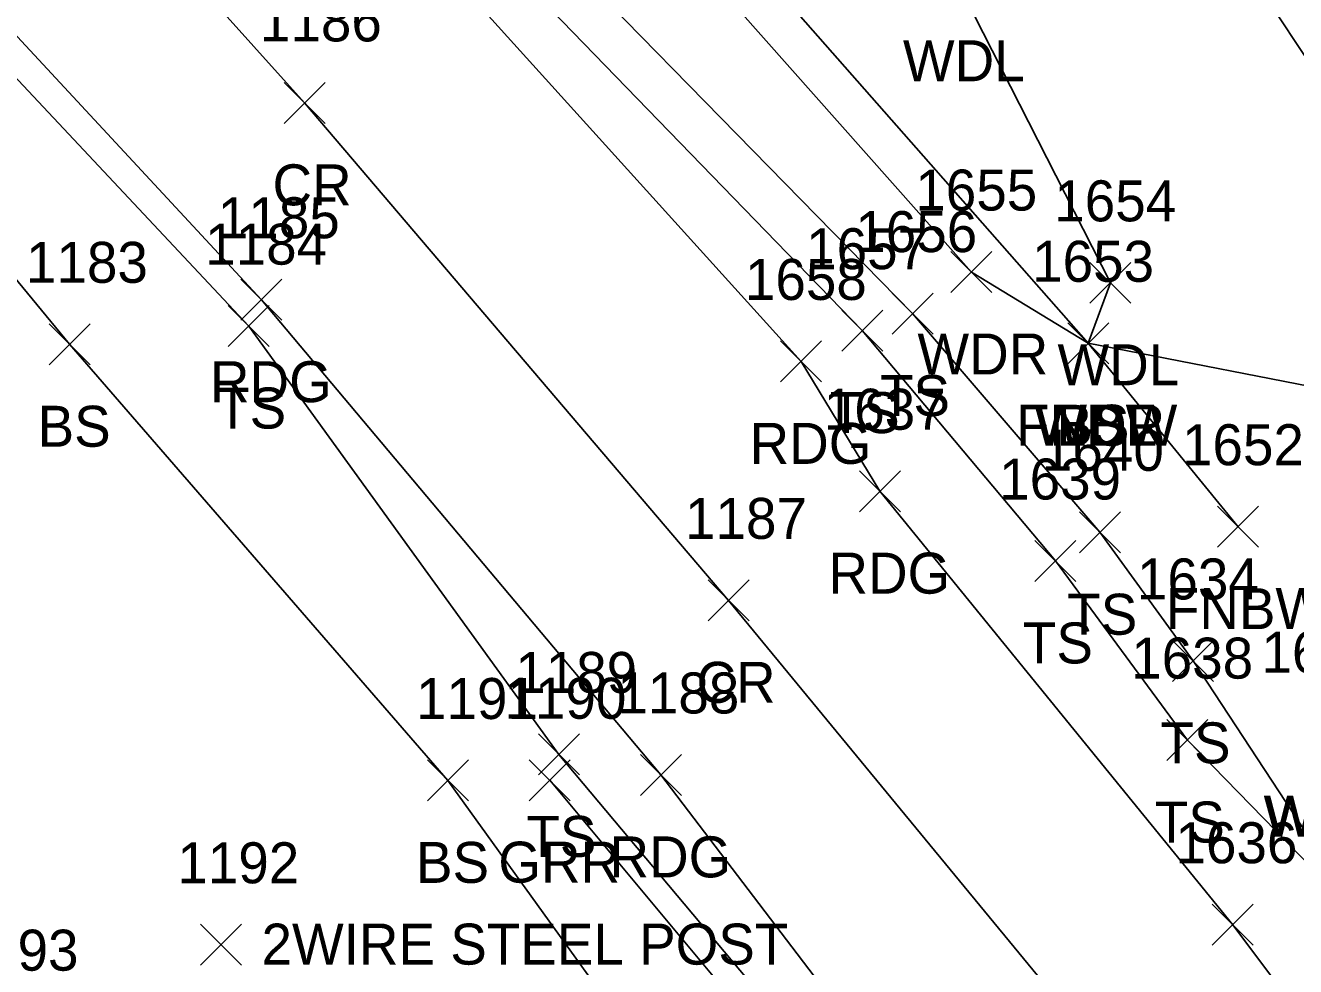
# Model space of a CAD drawing. Extents: x 1469310 to 1475157, y 493997 to 498873.
# Drawn here: x 1469498.4 to 1469560.4, y 498605.4 to 498651.4 of the extents above; entities that cross this region are included whole.
import ezdxf

# ---------------------------------------------------------------- set-up
doc = ezdxf.new("R2010")
doc.units = 0
for name, color, linetype in [('L_A', 7, 'Continuous'), ('L_I', 7, 'Continuous'), ('L_TIC', 7, 'Continuous'), ('LAWA', 7, 'Continuous'), ('LELB', 7, 'Continuous'), ('LFNC', 7, 'Continuous'), ('P_A', 7, 'Continuous'), ('P_I', 7, 'Continuous'), ('P_TIC', 7, 'Continuous'), ('PEU', 7, 'Continuous'), ('PRC', 7, 'Continuous'), ('R_A', 7, 'Continuous'), ('R_C', 7, 'Continuous'), ('R_I', 7, 'Continuous'), ('R_TIC', 7, 'Continuous'), ('RGR', 7, 'Continuous')]:
    doc.layers.add(name, color=color, linetype=linetype)

msp = doc.modelspace()

# ---------------------------------------------------------------- linework, layer by layer
at = {"layer": 'L_TIC'}
for points in [[(1469543.555, 498638.347), (1469545.555, 498640.347)], [(1469545.555, 498638.347), (1469543.555, 498640.347)], [(1469550.335, 498637.82), (1469552.335, 498639.82)], [(1469552.335, 498637.82), (1469550.335, 498639.82)], [(1469540.68, 498636.319), (1469542.68, 498638.319)], [(1469542.68, 498636.319), (1469540.68, 498638.319)], [(1469508.281, 498635.708), (1469510.281, 498637.708)], [(1469510.281, 498635.708), (1469508.281, 498637.708)], [(1469538.227, 498635.486), (1469540.227, 498637.486)], [(1469540.227, 498635.486), (1469538.227, 498637.486)], [(1469499.535, 498634.821), (1469501.535, 498636.821)], [(1469501.535, 498634.821), (1469499.535, 498636.821)], [(1469549.256, 498634.871), (1469551.256, 498636.871)], [(1469551.256, 498634.871), (1469549.256, 498636.871)], [(1469549.256, 498634.871), (1469551.256, 498636.871)], [(1469551.256, 498634.871), (1469549.256, 498636.871)], [(1469549.256, 498634.871), (1469551.256, 498636.871)], [(1469551.256, 498634.871), (1469549.256, 498636.871)], [(1469549.256, 498634.871), (1469551.256, 498636.871)], [(1469551.256, 498634.871), (1469549.256, 498636.871)], [(1469556.57, 498625.919), (1469558.57, 498627.919)], [(1469558.57, 498625.919), (1469556.57, 498627.919)], [(1469549.821, 498625.646), (1469551.821, 498627.646)], [(1469551.821, 498625.646), (1469549.821, 498627.646)], [(1469547.655, 498624.245), (1469549.655, 498626.245)], [(1469549.655, 498624.245), (1469547.655, 498626.245)], [(1469554.371, 498619.368), (1469556.371, 498621.368)], [(1469556.371, 498619.368), (1469554.371, 498621.368)], [(1469554.093, 498615.504), (1469556.093, 498617.504)], [(1469556.093, 498615.504), (1469554.093, 498617.504)], [(1469523.422, 498614.805), (1469525.422, 498616.805)], [(1469525.422, 498614.805), (1469523.422, 498616.805)], [(1469518.003, 498613.534), (1469520.003, 498615.534)], [(1469520.003, 498613.534), (1469518.003, 498615.534)], [(1469506.922, 498605.516), (1469508.922, 498607.516)], [(1469508.922, 498605.516), (1469506.922, 498607.516)]]:
    msp.add_lwpolyline(points, dxfattribs=at)
at = {"layer": 'LAWA'}
for points in [[(1469550.256, 498635.871), (1469551.335, 498638.82), (1469543.791, 498653.658), (1469517.004, 498693.687), (1469493.697, 498717.291), (1469464.727, 498743.888), (1469442.449, 498767.361), (1469415.626, 498791.262), (1469396.511, 498809.173), (1469374.233, 498838.066)], [(1469550.256, 498635.871), (1469544.555, 498639.347), (1469529.257, 498656.591), (1469521.268, 498666.888), (1469499.096, 498691), (1469482.906, 498705.537), (1469469.317, 498718.602), (1469451.077, 498739.432), (1469431.272, 498758.582), (1469415.669, 498776.754), (1469392.183, 498799.734), (1469384.544, 498811.213)]]:
    msp.add_lwpolyline(points, dxfattribs=at)
at = {"layer": 'LELB'}
for points in [[(1469689.874, 498657.87), (1469664.198, 498669.39), (1469609.729, 498671.933), (1469582.144, 498658.759), (1469563.399, 498646.025), (1469554.478, 498659.448), (1469546.055, 498676.671), (1469525.383, 498698.234), (1469503.854, 498725.442), (1469472.452, 498754.543), (1469455.127, 498777.294), (1469419.867, 498802.33), (1469400.99, 498819.039), (1469383.055, 498844.763)], [(1469596.337, 498559.709), (1469578.349, 498585.399), (1469563.744, 498607.627), (1469555.371, 498620.368), (1469550.821, 498626.646), (1469541.68, 498637.319), (1469517.52, 498662.002), (1469494.243, 498687.266), (1469477.199, 498705.84), (1469448.358, 498735.299), (1469427.592, 498756.343), (1469413.618, 498771.296), (1469390.023, 498797.181), (1469364.143, 498823.885)], [(1469563.744, 498607.627), (1469555.093, 498616.504), (1469548.655, 498625.245), (1469539.227, 498636.486), (1469516.208, 498660.231), (1469491.998, 498685.049), (1469474.245, 498704.181), (1469446.062, 498733.487), (1469425.868, 498754.547), (1469411.994, 498769.104), (1469387.947, 498794.99), (1469362.089, 498822.046)], [(1469416.823, 498734.314), (1469446.326, 498703.097), (1469470.885, 498677.648), (1469509.281, 498636.708), (1469524.422, 498615.805), (1469544.375, 498592.02), (1469564.878, 498563.16), (1469574.599, 498542.858), (1469576.567, 498532.675), (1469562.977, 498525.948), (1469548.2, 498517.369), (1469540.614, 498511.222), (1469554.066, 498484.991), (1469566.508, 498459.59)], [(1469413.419, 498730.944), (1469442.517, 498698.703), (1469468.453, 498674.773), (1469500.535, 498635.821), (1469519.003, 498614.534), (1469533.172, 498594.862), (1469544.52, 498587.119), (1469562.893, 498554.703), (1469567.788, 498543.524), (1469559.261, 498528.602), (1469545.395, 498521.66), (1469536.791, 498513.026)], [(1469563.61, 498633.273), (1469550.256, 498635.871)]]:
    msp.add_lwpolyline(points, dxfattribs=at)
at = {"layer": 'LFNC'}
msp.add_lwpolyline([(1469557.57, 498626.919), (1469550.256, 498635.871), (1469522.293, 498667.624), (1469500.255, 498692.907), (1469472.784, 498720.334), (1469454.313, 498738.912), (1469435.585, 498759.186), (1469416.3, 498780.923), (1469395.195, 498801.33), (1469384.544, 498811.213), (1469367.117, 498829.454)], dxfattribs=at)
at = {"layer": 'P_TIC'}
for points in [[(1469511.008, 498646.602), (1469513.008, 498648.602)], [(1469513.008, 498646.602), (1469511.008, 498648.602)], [(1469508.9, 498636.995), (1469510.9, 498638.995)], [(1469510.9, 498636.995), (1469508.9, 498638.995)], [(1469535.237, 498633.985), (1469537.237, 498635.985)], [(1469537.237, 498633.985), (1469535.237, 498635.985)], [(1469539.085, 498627.651), (1469541.085, 498629.651)], [(1469541.085, 498627.651), (1469539.085, 498629.651)], [(1469531.7, 498622.323), (1469533.7, 498624.323)], [(1469533.7, 498622.323), (1469531.7, 498624.323)], [(1469528.399, 498613.803), (1469530.399, 498615.803)], [(1469530.399, 498613.803), (1469528.399, 498615.803)], [(1469556.307, 498606.493), (1469558.307, 498608.493)], [(1469558.307, 498606.493), (1469556.307, 498608.493)]]:
    msp.add_lwpolyline(points, dxfattribs=at)
at = {"layer": 'PEU'}
for points in [[(1469787.287, 498391.186), (1469770.786, 498403.186), (1469744.942, 498420.511), (1469711.225, 498443.774), (1469680.07, 498463.208), (1469651.576, 498483.407), (1469630.626, 498501.518), (1469612.52, 498523.24), (1469599.406, 498542.19), (1469591.57, 498556.602), (1469575.608, 498583.062), (1469557.307, 498607.493), (1469540.085, 498628.651), (1469536.237, 498634.985), (1469514.981, 498658.506), (1469490.833, 498684.266), (1469472.689, 498702.569), (1469444.888, 498732.157), (1469424.966, 498753.74), (1469411.282, 498767.744), (1469386.832, 498794.065), (1469360.465, 498820.438)], [(1469418.156, 498735.543), (1469447.908, 498704.219), (1469471.825, 498679.031), (1469509.9, 498637.995), (1469529.399, 498614.803), (1469545.139, 498594.127), (1469565.651, 498563.085), (1469576.412, 498543.24), (1469581.129, 498534.677), (1469591.748, 498510.077), (1469602.71, 498485.38), (1469609.033, 498458.441), (1469615.466, 498438.565), (1469621.976, 498404.809), (1469621.719, 498400.421), (1469625.378, 498362.571), (1469626.198, 498333.717)]]:
    msp.add_lwpolyline(points, dxfattribs=at)
at = {"layer": 'PRC'}
msp.add_lwpolyline([(1469423.494, 498741.591), (1469452.569, 498710.453), (1469477.957, 498685.461), (1469512.008, 498647.602), (1469532.7, 498623.323), (1469554.784, 498596.501), (1469570.656, 498571.785), (1469585.254, 498547.179), (1469603.312, 498509.955), (1469610.701, 498488.938), (1469623.702, 498439.145), (1469630.721, 498407.825), (1469631.037, 498401.913), (1469634.459, 498363.902), (1469634.516, 498333.309)], dxfattribs=at)
at = {"layer": 'R_TIC'}
for points in [[(1469522.975, 498613.546), (1469524.975, 498615.546)], [(1469524.975, 498613.546), (1469522.975, 498615.546)]]:
    msp.add_lwpolyline(points, dxfattribs=at)
at = {"layer": 'RGR'}
msp.add_lwpolyline([(1469523.975, 498614.546), (1469543.903, 498590.637), (1469565.017, 498560.783), (1469572.552, 498542.581)], dxfattribs=at)

# ---------------------------------------------------------------- texts
at = {"layer": 'L_A'}
for s, p in [('WDL', (1469541.208, 498648.658)), ('WDR', (1469541.917, 498634.347)), ('WDL', (1469548.753, 498633.82)), ('TS', (1469540.089, 498632.319)), ('TS', (1469507.69, 498631.708)), ('TS', (1469537.636, 498631.486)), ('BS', (1469498.976, 498630.821)), ('FNBW', (1469546.729, 498630.871)), ('WDR', (1469547.619, 498630.871)), ('WDL', (1469547.674, 498630.871)), ('BS', (1469548.697, 498630.871)), ('TS', (1469549.23, 498621.646)), ('FNBW', (1469554.043, 498621.919)), ('TS', (1469547.064, 498620.245)), ('TS', (1469553.781, 498615.368)), ('WDR', (1469558.811, 498611.788)), ('WDL', (1469558.866, 498611.788)), ('TS', (1469553.503, 498611.504)), ('TS', (1469522.832, 498610.805)), ('BS', (1469517.444, 498609.534))]:
    msp.add_text(s, height=2, dxfattribs=at).set_placement(p)
at = {"layer": 'L_I'}
for s, p in [('1655', (1469541.815, 498642.347)), ('1654', (1469548.595, 498641.82)), ('1656', (1469538.885, 498640.319)), ('1184', (1469507.155, 498639.708)), ('1657', (1469536.487, 498639.486)), ('1183', (1469498.409, 498638.821)), ('1653', (1469547.516, 498638.871)), ('1653', (1469547.516, 498638.871)), ('1653', (1469547.516, 498638.871)), ('1653', (1469547.516, 498638.871)), ('1640', (1469547.994, 498629.646)), ('1652', (1469554.83, 498629.919)), ('1639', (1469545.907, 498628.245)), ('1634', (1469552.631, 498623.368)), ('1635', (1469558.709, 498619.788)), ('1635', (1469558.709, 498619.788)), ('1638', (1469552.353, 498619.504)), ('1189', (1469522.289, 498618.805)), ('1191', (1469517.444, 498617.534)), ('1192', (1469505.796, 498609.516)), ('1193', (1469495.022, 498605.251))]:
    msp.add_text(s, height=2, dxfattribs=at).set_placement(p)
at = {"layer": 'P_A'}
for s, p in [('CR', (1469510.441, 498642.602)), ('RDG', (1469507.388, 498632.995)), ('RDG', (1469533.725, 498629.985)), ('RDG', (1469537.574, 498623.651)), ('CR', (1469531.133, 498618.323)), ('RDG', (1469526.887, 498609.803))]:
    msp.add_text(s, height=2, dxfattribs=at).set_placement(p)
at = {"layer": 'P_I'}
for s, p in [('1186', (1469509.827, 498650.602)), ('1185', (1469507.774, 498640.995)), ('1658', (1469533.497, 498637.985)), ('1637', (1469537.345, 498631.651)), ('1187', (1469530.574, 498626.323)), ('1188', (1469527.273, 498617.803)), ('1636', (1469554.512, 498610.493))]:
    msp.add_text(s, height=2, dxfattribs=at).set_placement(p)
at = {"layer": 'R_A'}
msp.add_text('GRR', height=2, dxfattribs=at).set_placement((1469521.463, 498609.546))
at = {"layer": 'R_C'}
msp.add_text('2WIRE STEEL POST', height=2, dxfattribs=at).set_placement((1469509.904, 498605.546))
at = {"layer": 'R_I'}
msp.add_text('1190', height=2, dxfattribs=at).set_placement((1469521.762, 498617.546))

doc.saveas('drawing.dxf')
